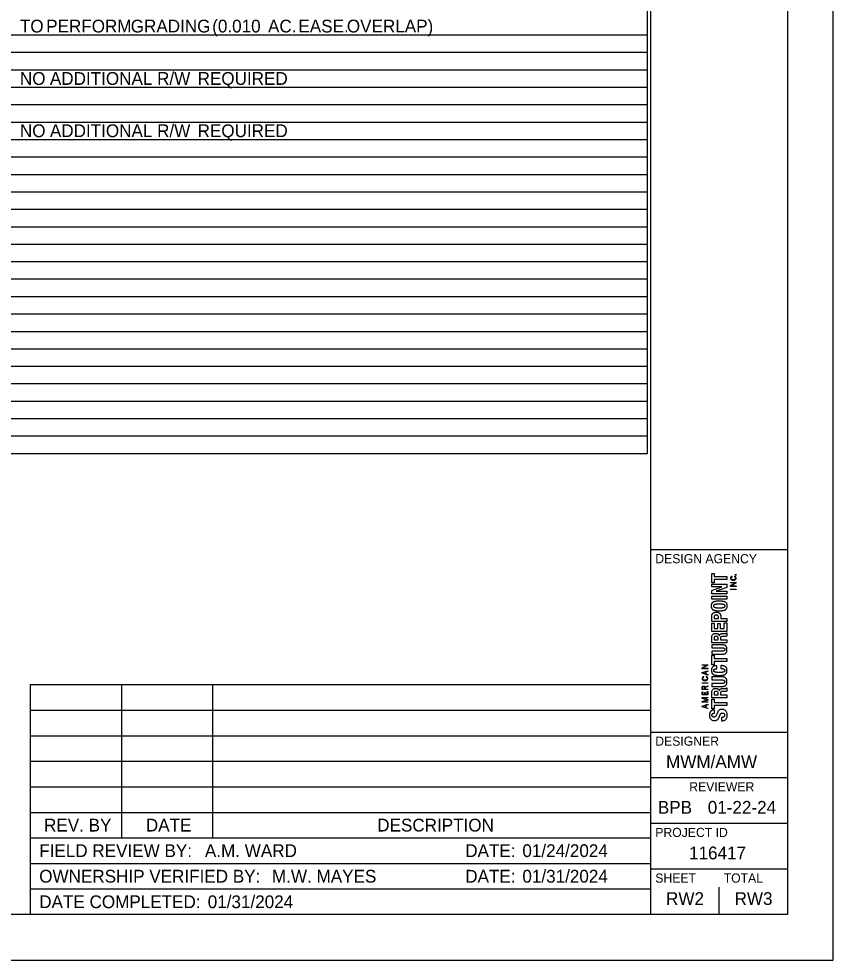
# Model space of a CAD drawing. Extents: x 0 to 34, y 0 to 22.
# Drawn here: x 25.07 to 34, y 0 to 10.32 of the extents above; entities that cross this region are included whole.
import ezdxf

# ---------------------------------------------------------------- set-up
doc = ezdxf.new("R2010")
doc.units = 0
for name, color, linetype in [('Default', 7, 'Continuous'), ('SH_Border', 7, 'Continuous'), ('SH_Cut_Line', 7, 'Continuous'), ('SH_Data', 7, 'Continuous'), ('SH_Text', 7, 'Continuous')]:
    doc.layers.add(name, color=color, linetype=linetype)

msp = doc.modelspace()

# ---------------------------------------------------------------- linework, layer by layer
at = {"layer": 'Default'}
for p, q in [((31.964, 5.554), (31.964, 16.637)), ((1.5, 10.14), (31.964, 10.14)), ((1.5, 9.949), (31.964, 9.949)), ((1.5, 9.758), (31.964, 9.758)), ((1.5, 9.567), (31.964, 9.567)), ((1.5, 9.376), (31.964, 9.376)), ((1.5, 9.185), (31.964, 9.185)), ((1.5, 8.993), (31.964, 8.993)), ((1.5, 8.802), (31.964, 8.802)), ((1.5, 8.611), (31.964, 8.611)), ((1.5, 8.42), (31.964, 8.42)), ((1.5, 8.229), (31.964, 8.229)), ((1.5, 8.038), (31.964, 8.038)), ((1.5, 7.847), (31.964, 7.847)), ((1.5, 7.656), (31.964, 7.656)), ((1.5, 7.465), (31.964, 7.465)), ((1.5, 7.274), (31.964, 7.274)), ((1.5, 7.082), (31.964, 7.082)), ((1.5, 6.891), (31.964, 6.891)), ((1.5, 6.7), (31.964, 6.7)), ((1.5, 6.509), (31.964, 6.509)), ((1.5, 6.318), (31.964, 6.318)), ((1.5, 6.127), (31.964, 6.127)), ((1.5, 5.936), (31.964, 5.936)), ((1.5, 5.745), (31.964, 5.745)), ((1.5, 5.554), (31.964, 5.554))]:
    msp.add_line(p, q, dxfattribs=at)
at = {"layer": 'SH_Border'}
for p, q in [((32, 0.5), (32, 21.5)), ((32, 4.5), (33.5, 4.5)), ((32, 2.5), (33.5, 2.5)), ((32, 2), (33.5, 2)), ((32, 1.5), (33.5, 1.5)), ((32, 1), (33.5, 1))]:
    msp.add_line(p, q, dxfattribs=at)
msp.add_lwpolyline([(1.5, 21.5), (33.5, 21.5), (33.5, 0.5), (1.5, 0.5)], close=True, dxfattribs=at)
at = {"layer": 'SH_Cut_Line'}
msp.add_lwpolyline([(0, 0), (34, 0), (34, 22), (0, 22)], close=True, dxfattribs=at)
at = {"layer": 'SH_Data'}
for p, q in [((32.75, 3.5), (32.75, 3.5)), ((32.75, 3.5), (32.75, 3.5)), ((32.75, 0.5), (32.75, 0.8)), ((32.375, 0.675), (32.375, 0.675))]:
    msp.add_line(p, q, dxfattribs=at)
for points in [[(32.67, 4.239), (32.697, 4.239), (32.697, 4.204), (32.833, 4.204), (32.833, 4.171), (32.697, 4.171), (32.697, 4.135), (32.67, 4.135), (32.67, 4.239)], [(32.875, 4.096), (32.875, 4.105), (32.925, 4.134), (32.925, 4.134), (32.875, 4.134), (32.875, 4.139), (32.935, 4.139), (32.935, 4.134), (32.88, 4.102), (32.88, 4.101), (32.935, 4.101), (32.935, 4.096), (32.875, 4.096)], [(32.935, 4.218), (32.927, 4.218), (32.927, 4.225), (32.935, 4.225), (32.935, 4.218)], [(32.67, 4.051), (32.781, 4.091), (32.781, 4.092), (32.67, 4.092), (32.67, 4.122), (32.833, 4.122), (32.833, 4.084), (32.719, 4.044), (32.719, 4.044), (32.833, 4.044), (32.833, 4.013), (32.67, 4.013), (32.67, 4.051)], [(32.875, 4.061), (32.875, 4.067), (32.935, 4.067), (32.935, 4.061), (32.875, 4.061)], [(32.833, 3.957), (32.67, 3.957), (32.67, 3.99), (32.833, 3.99), (32.833, 3.957)], [(32.833, 3.712), (32.67, 3.712), (32.67, 3.769)], [(32.694, 3.744), (32.743, 3.744), (32.743, 3.759)], [(32.694, 3.758), (32.694, 3.744)], [(32.768, 3.762), (32.768, 3.744), (32.833, 3.744), (32.833, 3.712)], [(32.67, 3.694), (32.697, 3.694), (32.697, 3.635), (32.735, 3.635), (32.735, 3.69), (32.762, 3.69), (32.762, 3.635), (32.806, 3.635), (32.806, 3.696), (32.833, 3.696), (32.833, 3.603), (32.67, 3.603), (32.67, 3.694)], [(32.833, 3.476), (32.67, 3.476), (32.67, 3.537)], [(32.694, 3.525), (32.694, 3.509)], [(32.694, 3.509), (32.741, 3.509), (32.741, 3.523)], [(32.752, 3.554), (32.752, 3.554)], [(32.764, 3.527), (32.764, 3.509), (32.833, 3.509), (32.833, 3.476)], [(32.816, 3.548), (32.784, 3.547)], [(32.832, 3.587), (32.833, 3.587), (32.833, 3.552)], [(32.67, 3.341), (32.697, 3.341), (32.697, 3.305), (32.833, 3.305), (32.833, 3.273), (32.697, 3.273), (32.697, 3.237), (32.67, 3.237), (32.67, 3.341)], [(32.565, 3.194), (32.565, 3.203), (32.615, 3.231), (32.615, 3.231), (32.565, 3.231), (32.565, 3.237), (32.625, 3.237), (32.625, 3.231), (32.569, 3.199), (32.569, 3.199), (32.625, 3.199), (32.625, 3.194), (32.565, 3.194)], [(32.625, 3.125), (32.565, 3.144), (32.565, 3.152), (32.625, 3.171), (32.625, 3.165), (32.605, 3.159), (32.605, 3.137), (32.625, 3.131), (32.625, 3.125)], [(32.601, 3.138), (32.601, 3.158), (32.569, 3.148), (32.569, 3.148), (32.601, 3.138)], [(32.565, 3.034), (32.565, 3.039), (32.625, 3.039), (32.625, 3.034), (32.565, 3.034)], [(32.596, 2.992), (32.625, 3.006), (32.625, 3), (32.597, 2.987), (32.597, 2.971), (32.625, 2.971), (32.625, 2.966), (32.565, 2.966), (32.565, 2.986)], [(32.625, 2.907), (32.565, 2.907), (32.565, 2.941), (32.569, 2.941), (32.569, 2.913), (32.591, 2.913), (32.591, 2.933), (32.596, 2.933), (32.596, 2.913), (32.62, 2.913), (32.62, 2.943), (32.625, 2.943), (32.625, 2.907)], [(32.569, 2.971), (32.593, 2.971), (32.593, 2.986)], [(32.569, 2.986), (32.569, 2.971)], [(32.833, 2.873), (32.67, 2.873), (32.67, 2.934)], [(32.694, 2.922), (32.694, 2.906)], [(32.694, 2.906), (32.741, 2.906), (32.741, 2.92)], [(32.752, 2.951), (32.752, 2.951)], [(32.764, 2.924), (32.764, 2.906), (32.833, 2.906), (32.833, 2.873)], [(32.816, 2.944), (32.784, 2.944)], [(32.832, 2.984), (32.833, 2.984), (32.833, 2.949)], [(32.625, 2.826), (32.565, 2.826), (32.565, 2.836), (32.615, 2.852), (32.615, 2.853), (32.565, 2.869), (32.565, 2.879), (32.625, 2.879), (32.625, 2.873), (32.569, 2.873), (32.569, 2.873), (32.625, 2.855), (32.625, 2.85), (32.569, 2.832), (32.569, 2.832), (32.625, 2.832), (32.625, 2.826)], [(32.625, 2.758), (32.565, 2.777), (32.565, 2.785), (32.625, 2.804), (32.625, 2.798), (32.605, 2.792), (32.605, 2.769), (32.625, 2.763), (32.625, 2.758)], [(32.601, 2.771), (32.601, 2.791), (32.569, 2.781), (32.569, 2.781), (32.601, 2.771)], [(32.67, 2.86), (32.697, 2.86), (32.697, 2.824), (32.833, 2.824), (32.833, 2.791), (32.697, 2.791), (32.697, 2.756), (32.67, 2.756), (32.67, 2.86)]]:
    msp.add_lwpolyline(points, dxfattribs=at)
for points in [[(32.893, 4.201), (32.889, 4.199), (32.885, 4.197), (32.883, 4.195), (32.88, 4.193), (32.879, 4.19), (32.879, 4.186), (32.879, 4.183), (32.88, 4.181), (32.881, 4.178), (32.882, 4.176), (32.884, 4.175), (32.887, 4.173), (32.889, 4.172), (32.892, 4.171), (32.895, 4.17), (32.898, 4.169), (32.902, 4.169), (32.905, 4.169), (32.909, 4.169), (32.912, 4.169), (32.915, 4.17), (32.919, 4.171), (32.921, 4.172), (32.924, 4.173), (32.926, 4.175), (32.928, 4.176), (32.929, 4.179), (32.931, 4.181), (32.931, 4.184), (32.931, 4.187), (32.931, 4.189), (32.931, 4.191), (32.93, 4.193), (32.929, 4.194), (32.928, 4.196), (32.927, 4.197), (32.926, 4.198), (32.924, 4.199), (32.922, 4.2), (32.921, 4.2), (32.919, 4.201), (32.917, 4.202), (32.917, 4.202), (32.918, 4.207), (32.918, 4.207), (32.92, 4.206), (32.923, 4.205), (32.925, 4.204), (32.927, 4.203), (32.929, 4.202), (32.931, 4.2), (32.932, 4.199), (32.934, 4.197), (32.934, 4.195), (32.935, 4.192), (32.936, 4.19), (32.936, 4.187), (32.936, 4.183), (32.935, 4.18), (32.934, 4.177), (32.932, 4.174), (32.93, 4.172), (32.927, 4.17), (32.925, 4.168), (32.921, 4.166), (32.918, 4.165), (32.914, 4.164), (32.91, 4.164), (32.905, 4.164), (32.901, 4.164), (32.896, 4.164), (32.893, 4.165), (32.889, 4.166), (32.886, 4.168), (32.883, 4.17), (32.88, 4.172), (32.878, 4.174), (32.877, 4.177), (32.875, 4.18), (32.875, 4.183), (32.875, 4.187), (32.875, 4.189), (32.875, 4.192), (32.876, 4.194), (32.877, 4.196), (32.878, 4.198), (32.88, 4.199), (32.881, 4.201), (32.883, 4.202), (32.885, 4.203), (32.887, 4.204), (32.889, 4.205), (32.892, 4.206), (32.892, 4.206), (32.893, 4.201), (32.893, 4.201)], [(32.751, 3.826), (32.739, 3.826), (32.727, 3.826), (32.717, 3.828), (32.706, 3.829), (32.697, 3.831), (32.69, 3.835), (32.682, 3.839), (32.677, 3.845), (32.672, 3.852), (32.668, 3.859), (32.666, 3.869), (32.666, 3.882), (32.666, 3.894), (32.668, 3.904), (32.672, 3.911), (32.677, 3.918), (32.682, 3.924), (32.69, 3.928), (32.697, 3.932), (32.706, 3.934), (32.717, 3.936), (32.727, 3.937), (32.739, 3.937), (32.751, 3.937), (32.758, 3.937), (32.764, 3.937), (32.771, 3.937)], [(32.771, 3.937), (32.776, 3.936), (32.781, 3.936), (32.785, 3.936), (32.796, 3.934), (32.805, 3.932), (32.812, 3.928), (32.82, 3.924), (32.825, 3.918), (32.83, 3.911), (32.834, 3.904), (32.836, 3.894), (32.836, 3.882), (32.836, 3.869), (32.834, 3.859), (32.83, 3.852), (32.825, 3.845), (32.82, 3.839), (32.812, 3.835), (32.805, 3.831), (32.796, 3.829), (32.785, 3.828), (32.775, 3.826), (32.763, 3.826), (32.751, 3.826)], [(32.751, 3.859), (32.762, 3.859), (32.771, 3.859), (32.779, 3.859), (32.787, 3.86), (32.793, 3.861), (32.798, 3.863), (32.803, 3.864), (32.806, 3.867), (32.808, 3.87), (32.81, 3.873), (32.812, 3.877), (32.812, 3.882), (32.812, 3.886), (32.81, 3.89), (32.808, 3.893), (32.806, 3.896), (32.803, 3.899), (32.798, 3.9), (32.793, 3.902), (32.787, 3.903), (32.779, 3.904), (32.771, 3.904), (32.762, 3.904), (32.751, 3.904), (32.74, 3.904), (32.731, 3.904), (32.723, 3.904), (32.716, 3.903), (32.709, 3.902), (32.704, 3.9), (32.7, 3.899), (32.696, 3.896), (32.694, 3.893), (32.692, 3.89), (32.691, 3.886), (32.691, 3.882), (32.691, 3.877), (32.692, 3.873), (32.694, 3.87), (32.696, 3.867), (32.7, 3.864), (32.704, 3.863), (32.709, 3.861), (32.716, 3.86), (32.723, 3.859), (32.731, 3.859), (32.74, 3.859), (32.751, 3.859)], [(32.67, 3.769), (32.67, 3.777), (32.671, 3.784), (32.674, 3.79), (32.677, 3.796), (32.68, 3.8), (32.685, 3.804), (32.689, 3.807), (32.695, 3.81), (32.701, 3.812), (32.706, 3.813), (32.712, 3.814), (32.719, 3.814), (32.727, 3.814), (32.734, 3.813), (32.741, 3.81), (32.747, 3.808), (32.752, 3.804), (32.756, 3.8), (32.76, 3.795), (32.763, 3.79), (32.765, 3.783), (32.767, 3.777), (32.768, 3.77), (32.768, 3.762)], [(32.743, 3.759), (32.743, 3.766), (32.741, 3.771), (32.737, 3.775), (32.733, 3.779), (32.727, 3.781), (32.719, 3.781), (32.711, 3.781), (32.705, 3.779), (32.7, 3.776), (32.696, 3.772), (32.694, 3.766), (32.694, 3.758)], [(32.67, 3.537), (32.67, 3.551), (32.673, 3.562), (32.68, 3.569), (32.687, 3.577), (32.698, 3.581), (32.712, 3.581), (32.723, 3.581), (32.732, 3.579), (32.739, 3.574), (32.745, 3.57), (32.75, 3.563), (32.752, 3.554)], [(32.741, 3.523), (32.741, 3.531), (32.739, 3.537), (32.735, 3.542), (32.732, 3.546), (32.725, 3.548), (32.717, 3.548), (32.702, 3.548), (32.694, 3.54), (32.694, 3.525)], [(32.752, 3.554), (32.753, 3.559), (32.755, 3.564), (32.757, 3.567), (32.759, 3.571), (32.762, 3.573), (32.766, 3.575), (32.769, 3.577), (32.774, 3.578), (32.78, 3.579), (32.786, 3.58), (32.794, 3.58), (32.802, 3.58), (32.811, 3.58), (32.818, 3.581), (32.822, 3.582), (32.827, 3.582), (32.83, 3.584), (32.832, 3.587)], [(32.784, 3.547), (32.778, 3.546), (32.773, 3.545), (32.769, 3.542), (32.766, 3.539), (32.764, 3.534), (32.764, 3.527)], [(32.833, 3.552), (32.831, 3.55), (32.828, 3.549), (32.825, 3.549), (32.822, 3.548), (32.819, 3.548), (32.816, 3.548)], [(32.67, 3.385), (32.67, 3.385), (32.783, 3.385), (32.783, 3.385), (32.787, 3.385), (32.791, 3.385), (32.795, 3.386), (32.798, 3.387), (32.801, 3.388), (32.803, 3.389), (32.806, 3.39), (32.808, 3.392), (32.809, 3.395), (32.811, 3.397), (32.812, 3.401), (32.812, 3.404), (32.812, 3.408), (32.811, 3.411), (32.809, 3.414), (32.808, 3.417), (32.806, 3.418), (32.803, 3.42), (32.801, 3.421), (32.798, 3.422), (32.795, 3.423), (32.791, 3.423), (32.787, 3.424), (32.783, 3.424), (32.783, 3.424), (32.67, 3.424), (32.67, 3.424), (32.67, 3.424), (32.67, 3.457), (32.67, 3.457), (32.67, 3.457), (32.783, 3.457), (32.783, 3.457), (32.794, 3.457), (32.802, 3.455), (32.809, 3.452), (32.816, 3.449), (32.821, 3.445), (32.825, 3.441), (32.829, 3.436), (32.832, 3.43), (32.834, 3.424), (32.835, 3.418), (32.836, 3.411), (32.836, 3.404), (32.836, 3.398), (32.835, 3.391), (32.834, 3.385), (32.833, 3.379), (32.83, 3.373), (32.826, 3.368), (32.822, 3.363), (32.817, 3.36), (32.81, 3.357), (32.803, 3.354), (32.794, 3.352), (32.783, 3.352), (32.783, 3.352), (32.67, 3.352), (32.67, 3.352), (32.67, 3.352), (32.67, 3.385), (32.67, 3.385)], [(32.725, 3.193), (32.713, 3.193), (32.704, 3.192), (32.699, 3.189), (32.693, 3.186), (32.691, 3.181), (32.691, 3.174), (32.691, 3.17), (32.692, 3.166), (32.694, 3.163), (32.696, 3.161), (32.7, 3.159), (32.705, 3.157), (32.71, 3.156), (32.716, 3.155), (32.724, 3.154), (32.732, 3.153), (32.742, 3.153), (32.753, 3.153), (32.766, 3.153), (32.776, 3.153), (32.783, 3.154), (32.791, 3.155), (32.797, 3.156), (32.801, 3.158), (32.805, 3.16), (32.808, 3.162), (32.809, 3.165), (32.811, 3.168), (32.812, 3.171), (32.812, 3.174), (32.812, 3.177), (32.811, 3.18), (32.81, 3.182), (32.809, 3.185), (32.807, 3.187), (32.804, 3.189), (32.801, 3.191), (32.797, 3.192), (32.792, 3.193), (32.786, 3.194), (32.779, 3.195), (32.77, 3.195), (32.77, 3.195), (32.77, 3.228), (32.77, 3.228), (32.779, 3.228), (32.787, 3.227), (32.795, 3.226), (32.803, 3.224), (32.81, 3.222), (32.816, 3.218), (32.822, 3.214), (32.827, 3.209), (32.831, 3.202), (32.834, 3.196), (32.836, 3.187), (32.836, 3.176), (32.836, 3.163), (32.834, 3.154), (32.83, 3.146), (32.825, 3.139), (32.82, 3.133), (32.812, 3.129), (32.805, 3.126), (32.796, 3.123), (32.785, 3.122), (32.775, 3.121), (32.763, 3.12), (32.751, 3.12), (32.739, 3.12), (32.727, 3.121), (32.717, 3.122), (32.706, 3.123), (32.697, 3.126), (32.69, 3.129), (32.682, 3.133), (32.677, 3.139), (32.672, 3.146), (32.668, 3.154), (32.666, 3.163), (32.666, 3.176), (32.666, 3.188), (32.668, 3.197), (32.672, 3.204), (32.676, 3.21), (32.681, 3.215), (32.687, 3.219), (32.692, 3.222), (32.699, 3.224), (32.706, 3.225), (32.712, 3.226), (32.719, 3.226), (32.725, 3.226), (32.725, 3.226), (32.725, 3.193), (32.725, 3.193)], [(32.582, 3.101), (32.578, 3.1), (32.575, 3.098), (32.572, 3.095), (32.57, 3.093), (32.569, 3.09), (32.569, 3.086), (32.569, 3.083), (32.569, 3.081), (32.571, 3.079), (32.572, 3.077), (32.574, 3.075), (32.576, 3.074), (32.579, 3.072), (32.581, 3.071), (32.585, 3.07), (32.588, 3.07), (32.591, 3.069), (32.595, 3.069), (32.598, 3.069), (32.602, 3.07), (32.605, 3.07), (32.608, 3.071), (32.611, 3.072), (32.613, 3.074), (32.616, 3.075), (32.618, 3.077), (32.619, 3.079), (32.62, 3.081), (32.621, 3.084), (32.621, 3.087), (32.621, 3.089), (32.62, 3.091), (32.62, 3.093), (32.619, 3.095), (32.618, 3.096), (32.617, 3.097), (32.615, 3.098), (32.614, 3.099), (32.612, 3.1), (32.61, 3.101), (32.608, 3.102), (32.606, 3.102), (32.606, 3.102), (32.607, 3.107), (32.607, 3.107), (32.61, 3.107), (32.612, 3.106), (32.615, 3.105), (32.617, 3.104), (32.619, 3.102), (32.62, 3.101), (32.622, 3.099), (32.623, 3.097), (32.624, 3.095), (32.625, 3.093), (32.625, 3.09), (32.625, 3.087), (32.625, 3.083), (32.625, 3.08), (32.623, 3.077), (32.622, 3.074), (32.62, 3.072), (32.617, 3.07), (32.614, 3.068), (32.611, 3.067), (32.607, 3.066), (32.604, 3.065), (32.599, 3.064), (32.595, 3.064), (32.59, 3.064), (32.586, 3.065), (32.582, 3.066), (32.579, 3.067), (32.575, 3.068), (32.573, 3.07), (32.57, 3.072), (32.568, 3.074), (32.566, 3.077), (32.565, 3.08), (32.564, 3.083), (32.564, 3.087), (32.564, 3.09), (32.565, 3.092), (32.566, 3.094), (32.566, 3.096), (32.568, 3.098), (32.569, 3.099), (32.571, 3.101), (32.572, 3.102), (32.575, 3.103), (32.577, 3.104), (32.579, 3.105), (32.581, 3.106), (32.581, 3.106), (32.582, 3.101), (32.582, 3.101)], [(32.67, 3.032), (32.67, 3.032), (32.783, 3.032), (32.783, 3.032), (32.787, 3.032), (32.791, 3.033), (32.795, 3.033), (32.798, 3.034), (32.801, 3.035), (32.803, 3.036), (32.806, 3.038), (32.808, 3.04), (32.809, 3.042), (32.811, 3.045), (32.812, 3.048), (32.812, 3.052), (32.812, 3.056), (32.811, 3.059), (32.809, 3.061), (32.808, 3.064), (32.806, 3.066), (32.803, 3.067), (32.801, 3.069), (32.798, 3.07), (32.795, 3.07), (32.791, 3.071), (32.787, 3.071), (32.783, 3.071), (32.783, 3.071), (32.67, 3.071), (32.67, 3.071), (32.67, 3.071), (32.67, 3.104), (32.67, 3.104), (32.67, 3.104), (32.783, 3.104), (32.783, 3.104), (32.794, 3.104), (32.802, 3.102), (32.809, 3.1), (32.816, 3.097), (32.821, 3.093), (32.825, 3.088), (32.829, 3.083), (32.832, 3.077), (32.834, 3.071), (32.835, 3.065), (32.836, 3.058), (32.836, 3.052), (32.836, 3.045), (32.835, 3.039), (32.834, 3.032), (32.833, 3.026), (32.83, 3.021), (32.826, 3.016), (32.822, 3.011), (32.817, 3.007), (32.81, 3.004), (32.803, 3.001), (32.794, 3), (32.783, 3), (32.783, 3), (32.67, 3), (32.67, 3), (32.67, 3), (32.67, 3.032), (32.67, 3.032)], [(32.565, 2.986), (32.565, 2.992), (32.566, 2.996), (32.569, 2.999), (32.572, 3.003), (32.576, 3.004), (32.581, 3.004), (32.585, 3.004), (32.588, 3.003), (32.591, 3.001), (32.593, 2.999), (32.595, 2.996), (32.596, 2.992)], [(32.593, 2.986), (32.593, 2.99), (32.592, 2.993), (32.59, 2.995), (32.588, 2.997), (32.585, 2.999), (32.581, 2.999), (32.577, 2.999), (32.575, 2.998), (32.573, 2.995), (32.57, 2.993), (32.569, 2.99), (32.569, 2.986)], [(32.67, 2.934), (32.67, 2.948), (32.673, 2.958), (32.68, 2.966), (32.687, 2.974), (32.698, 2.978), (32.712, 2.978), (32.723, 2.978), (32.732, 2.975), (32.739, 2.971), (32.745, 2.967), (32.75, 2.96), (32.752, 2.951)], [(32.741, 2.92), (32.741, 2.928), (32.739, 2.934), (32.735, 2.938), (32.732, 2.943), (32.725, 2.945), (32.717, 2.945), (32.702, 2.945), (32.694, 2.937), (32.694, 2.922)], [(32.752, 2.951), (32.753, 2.956), (32.755, 2.961), (32.757, 2.964), (32.759, 2.967), (32.762, 2.97), (32.766, 2.972), (32.769, 2.974), (32.774, 2.975), (32.78, 2.976), (32.786, 2.976), (32.794, 2.977), (32.802, 2.977), (32.811, 2.977), (32.818, 2.978), (32.822, 2.978), (32.827, 2.979), (32.83, 2.981), (32.832, 2.984)], [(32.784, 2.944), (32.778, 2.943), (32.773, 2.942), (32.769, 2.939), (32.766, 2.936), (32.764, 2.931), (32.764, 2.924)], [(32.833, 2.949), (32.831, 2.947), (32.828, 2.946), (32.825, 2.945), (32.822, 2.945), (32.819, 2.945), (32.816, 2.944)], [(32.775, 2.661), (32.775, 2.661), (32.781, 2.661), (32.781, 2.661), (32.785, 2.661), (32.789, 2.662), (32.793, 2.662), (32.796, 2.663), (32.799, 2.664), (32.801, 2.666), (32.804, 2.668), (32.806, 2.671), (32.807, 2.674), (32.809, 2.677), (32.809, 2.681), (32.809, 2.686), (32.809, 2.692), (32.807, 2.697), (32.804, 2.701), (32.8, 2.706), (32.794, 2.708), (32.786, 2.708), (32.782, 2.708), (32.779, 2.708), (32.776, 2.707), (32.773, 2.705), (32.77, 2.704), (32.767, 2.701), (32.765, 2.698), (32.763, 2.695), (32.761, 2.691), (32.759, 2.687), (32.757, 2.681), (32.755, 2.675), (32.752, 2.667), (32.749, 2.66), (32.745, 2.654), (32.742, 2.647), (32.738, 2.642), (32.734, 2.638), (32.73, 2.634), (32.725, 2.631), (32.719, 2.629), (32.713, 2.628), (32.706, 2.627), (32.699, 2.627), (32.68, 2.627), (32.667, 2.632), (32.658, 2.642), (32.649, 2.652), (32.644, 2.666), (32.644, 2.684), (32.644, 2.692), (32.645, 2.7), (32.647, 2.707), (32.649, 2.714), (32.651, 2.72), (32.656, 2.725), (32.66, 2.73), (32.665, 2.734), (32.671, 2.737), (32.677, 2.74), (32.685, 2.741), (32.694, 2.741), (32.694, 2.741), (32.699, 2.741), (32.699, 2.741), (32.699, 2.741), (32.699, 2.705), (32.699, 2.705), (32.69, 2.705), (32.683, 2.704), (32.679, 2.701), (32.674, 2.697), (32.671, 2.692), (32.671, 2.685), (32.671, 2.681), (32.672, 2.678), (32.673, 2.675), (32.675, 2.672), (32.676, 2.67), (32.678, 2.668), (32.68, 2.667), (32.682, 2.665), (32.685, 2.665), (32.688, 2.664), (32.69, 2.664), (32.693, 2.664), (32.699, 2.664), (32.704, 2.665), (32.707, 2.668), (32.711, 2.67), (32.715, 2.675), (32.718, 2.683), (32.718, 2.683), (32.731, 2.712), (32.731, 2.712), (32.734, 2.719), (32.737, 2.725), (32.74, 2.729), (32.744, 2.734), (32.747, 2.737), (32.751, 2.74), (32.755, 2.743), (32.76, 2.745), (32.764, 2.746), (32.769, 2.747), (32.774, 2.747), (32.78, 2.747), (32.799, 2.747), (32.814, 2.742), (32.823, 2.73), (32.832, 2.719), (32.837, 2.703), (32.837, 2.683), (32.837, 2.662), (32.832, 2.647), (32.823, 2.638), (32.813, 2.628), (32.8, 2.624), (32.783, 2.624), (32.783, 2.624), (32.775, 2.624), (32.775, 2.624), (32.775, 2.624), (32.775, 2.661), (32.775, 2.661)]]:
    msp.add_open_spline(points, degree=3, dxfattribs=at)
at = {"layer": 'SH_Text'}
for p, q in [((25.197, 3.02), (25.197, 0.5)), ((25.197, 3.02), (32, 3.02)), ((26.197, 3.02), (26.197, 1.34)), ((27.197, 3.02), (27.197, 1.34)), ((25.197, 2.74), (32, 2.74)), ((25.197, 2.46), (32, 2.46)), ((25.197, 2.18), (32, 2.18)), ((25.197, 1.9), (32, 1.9)), ((25.197, 1.62), (32, 1.62)), ((25.197, 1.34), (32, 1.34)), ((25.197, 1.06), (32, 1.06)), ((25.197, 0.78), (32, 0.78)), ((32, 0.5), (32, 0.5))]:
    msp.add_line(p, q, dxfattribs=at)

# ---------------------------------------------------------------- texts
at = {"layer": 'Default'}
for s, p in [('TO', (25.085, 10.166)), (' PERFORM', (25.321, 10.166)), (' GRADING', (26.248, 10.166)), (' (0.010', (27.141, 10.166)), (' AC.', (27.753, 10.166)), (' EASE.', (28.086, 10.166)), (' OVERLAP)', (28.617, 10.166)), ('NO', (25.085, 9.592)), (' ADDITIONAL', (25.362, 9.592)), (' R/W', (26.537, 9.592)), (' REQUIRED', (26.981, 9.592)), ('NO', (25.085, 9.019)), (' ADDITIONAL', (25.362, 9.019)), (' R/W', (26.537, 9.019)), (' REQUIRED', (26.981, 9.019))]:
    msp.add_text(s, height=0.14, dxfattribs=at).set_placement(p)
at = {"layer": 'SH_Data'}
for s, height, p in [('DESIGN AGENCY', 0.1, (32.05, 4.35)), ('DESIGNER', 0.1, (32.05, 2.35)), ('MWM/AMW', 0.14, (32.168, 2.105)), ('REVIEWER', 0.1, (32.422, 1.85)), ('BPB', 0.14, (32.078, 1.605)), ('01-22-24', 0.14, (32.625, 1.605)), ('PROJECT ID', 0.1, (32.05, 1.35)), ('116417', 0.14, (32.42, 1.105)), ('SHEET', 0.1, (32.05, 0.85)), ('TOTAL', 0.1, (32.8, 0.85)), ('RW2', 0.14, (32.168, 0.605)), ('RW3', 0.14, (32.919, 0.605))]:
    msp.add_text(s, height=height, dxfattribs=at).set_placement(p)
at = {"layer": 'SH_Text'}
for s, p in [('REV. BY', (25.35, 1.41)), ('DATE', (26.466, 1.41)), ('DESCRIPTION', (29.002, 1.41)), ('FIELD REVIEW BY:', (25.297, 1.13)), ('A.M. WARD', (27.113, 1.13)), ('DATE:', (29.967, 1.13)), ('01/24/2024', (30.593, 1.13)), ('OWNERSHIP VERIFIED BY:', (25.297, 0.85)), ('M.W. MAYES', (27.848, 0.85)), ('DATE:', (29.967, 0.85)), ('01/31/2024', (30.593, 0.85)), ('DATE COMPLETED:', (25.297, 0.57)), ('01/31/2024', (27.144, 0.57))]:
    msp.add_text(s, height=0.14, dxfattribs=at).set_placement(p)

doc.saveas('drawing.dxf')
